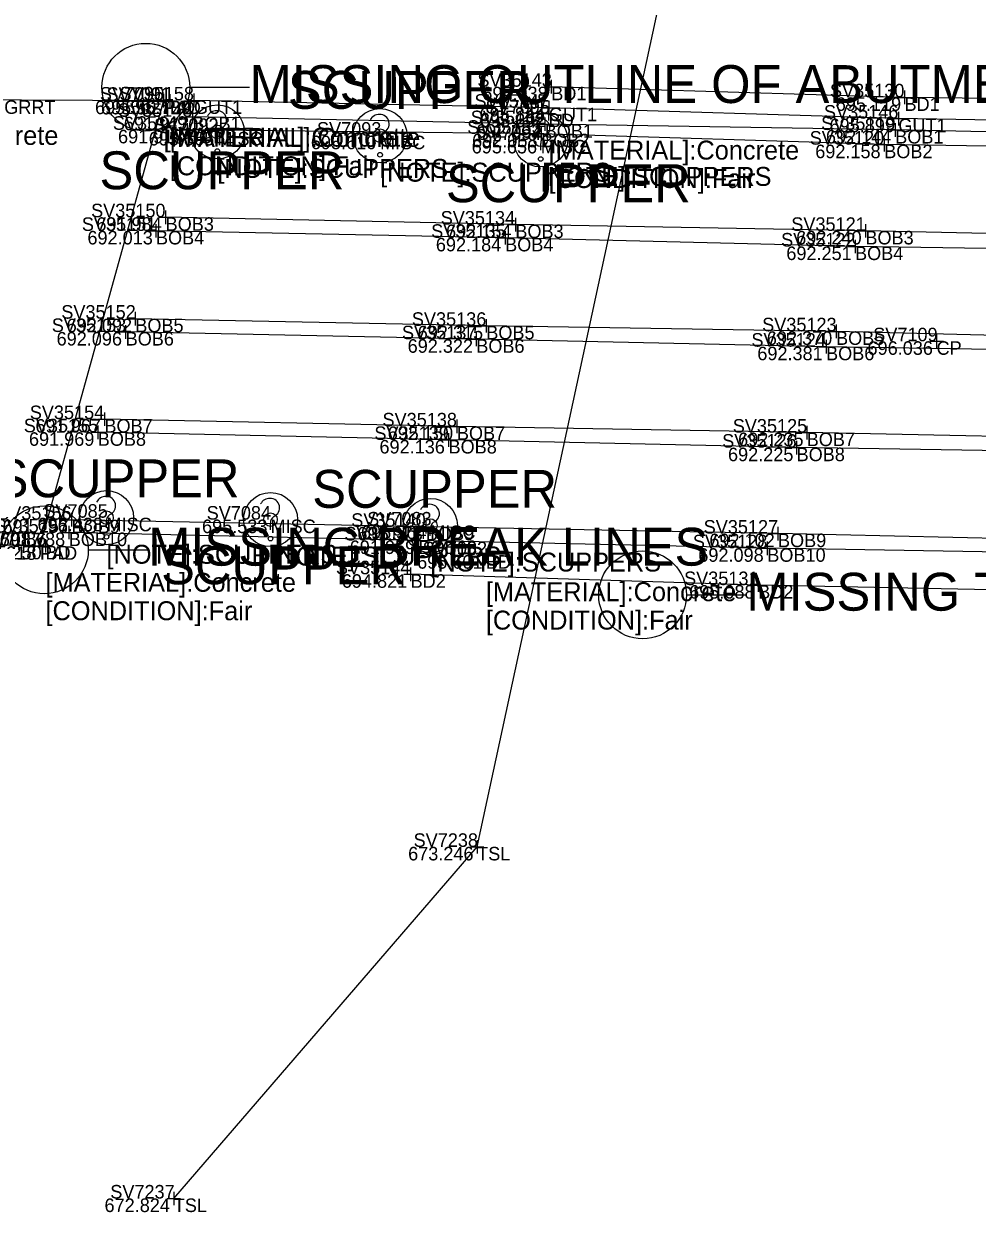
# Model space of a CAD drawing. Extents: x 1660019 to 1662995, y 619975 to 620342.
# Drawn here: x 1661226.1 to 1661296.6, y 620168.6 to 620256.5 of the extents above; entities that cross this region are included whole.
import ezdxf

# ---------------------------------------------------------------- set-up
doc = ezdxf.new("R2010")
doc.units = 0
for name, color, linetype in [('BR_X_Rail_Object', 7, 'Continuous'), ('BR_X_SV_Bottom_of_Beam', 7, 'Continuous'), ('BR_X_SV_Bottom_of_Beam_Text', 7, 'Continuous'), ('BR_X_SV_Deck_Top', 7, 'Continuous'), ('BR_X_SV_Deck_Top_Text', 7, 'Continuous'), ('PV_X_Curb', 7, 'Continuous'), ('RD_P_GR_Lt', 7, 'Continuous'), ('RD_X_Concrete_Pad', 7, 'Continuous'), ('RD_X_GR_Bar', 7, 'Continuous'), ('RD_X_Misc_Items', 7, 'Continuous'), ('RD_X_Text', 7, 'Continuous'), ('RD_X_Wall', 7, 'Continuous'), ('SC_Scratch6', 7, 'Continuous'), ('SV_X_Text', 7, 'Continuous'), ('SV_X_Toe_of_Slope', 7, 'Continuous')]:
    doc.layers.add(name, color=color, linetype=linetype)

msp = doc.modelspace()

# ---------------------------------------------------------------- linework, layer by layer
at = {"layer": 'BR_X_SV_Bottom_of_Beam'}
for points in [[(1661523.404, 620243.849), (1661497.415, 620244.383), (1661471.694, 620244.95), (1661445.773, 620245.45), (1661419.903, 620245.974), (1661394.009, 620246.51), (1661368.147, 620247.032), (1661342.287, 620247.488), (1661316.311, 620248.045), (1661290.557, 620248.602), (1661264.648, 620249.031), (1661238.6, 620249.579)], [(1661517.582, 620243.008), (1661496.897, 620243.44), (1661470.919, 620243.838), (1661445.09, 620244.441), (1661419.147, 620244.946), (1661393.26, 620245.417), (1661367.358, 620245.921), (1661341.629, 620246.518), (1661315.646, 620247.115), (1661289.746, 620247.518), (1661264.383, 620248.322), (1661238.204, 620248.614)], [(1661521.265, 620236.365), (1661495.332, 620236.959), (1661469.491, 620237.512), (1661443.572, 620237.996), (1661417.708, 620238.508), (1661391.884, 620239.08), (1661365.994, 620239.561), (1661340.119, 620240.034), (1661314.197, 620240.589), (1661288.354, 620241.145), (1661262.476, 620241.611), (1661236.623, 620242.15)], [(1661520.605, 620235.452), (1661494.63, 620235.975), (1661468.71, 620236.383), (1661442.944, 620236.996), (1661417.103, 620237.514), (1661391.103, 620237.982), (1661365.202, 620238.448), (1661339.374, 620239.07), (1661313.502, 620239.591), (1661287.59, 620239.99), (1661261.723, 620240.632), (1661235.908, 620241.144)], [(1661519.081, 620228.953), (1661493.234, 620229.438), (1661467.368, 620230.031), (1661441.422, 620230.57), (1661415.6, 620231.071), (1661389.731, 620231.651), (1661363.823, 620232.132), (1661337.817, 620232.613), (1661311.988, 620233.076), (1661286.183, 620233.721), (1661260.328, 620234.129), (1661234.382, 620234.656)], [(1661518.51, 620227.977), (1661492.527, 620228.475), (1661466.56, 620228.954), (1661440.742, 620229.56), (1661414.823, 620230.069), (1661388.938, 620230.522), (1661363.07, 620231.021), (1661337.298, 620231.612), (1661311.527, 620232.162), (1661285.446, 620232.587), (1661259.588, 620233.138), (1661233.669, 620233.674)], [(1661516.938, 620221.488), (1661491.079, 620222.019), (1661465.187, 620222.58), (1661439.251, 620223.092), (1661413.441, 620223.61), (1661387.584, 620224.174), (1661361.703, 620224.657), (1661335.742, 620225.126), (1661309.876, 620225.693), (1661284.015, 620226.238), (1661258.155, 620226.696), (1661232.1, 620227.235)], [(1661516.255, 620220.542), (1661490.624, 620220.907), (1661464.53, 620221.454), (1661438.64, 620222.101), (1661412.707, 620222.613), (1661386.76, 620223.066), (1661360.949, 620223.557), (1661335.05, 620224.176), (1661309.206, 620224.717), (1661283.267, 620225.126), (1661257.537, 620225.694), (1661231.605, 620226.262)], [(1661514.756, 620214.059), (1661488.914, 620214.555), (1661463.017, 620215.148), (1661437.126, 620215.616), (1661411.256, 620216.167), (1661385.428, 620216.691), (1661359.541, 620217.184), (1661333.602, 620217.682), (1661307.754, 620218.183), (1661281.891, 620218.773), (1661255.858, 620219.275), (1661229.67, 620219.799)], [(1661514.073, 620213.08), (1661488.21, 620213.597), (1661462.263, 620214.044), (1661436.515, 620214.643), (1661410.516, 620215.165), (1661384.602, 620215.601), (1661358.815, 620216.084), (1661332.968, 620216.701), (1661307.113, 620217.251), (1661281.101, 620217.691), (1661255.319, 620218.266), (1661229.464, 620218.851)]]:
    msp.add_lwpolyline(points, dxfattribs=at)
at = {"layer": 'BR_X_SV_Deck_Top'}
for points in [[(1661524.154, 620246.519), (1661498.291, 620247.067), (1661472.426, 620247.598), (1661446.524, 620248.074), (1661420.55, 620248.604), (1661394.772, 620249.021), (1661368.927, 620249.743), (1661342.743, 620250.117), (1661316.866, 620250.706), (1661291.246, 620251.013), (1661265.132, 620251.796)], [(1661513.529, 620210.295), (1661487.664, 620211.099), (1661461.66, 620211.354), (1661435.632, 620211.885), (1661409.962, 620212.424), (1661383.838, 620212.928), (1661332.298, 620213.947), (1661306.248, 620214.439), (1661280.429, 620214.969), (1661254.732, 620215.771)]]:
    msp.add_lwpolyline(points, dxfattribs=at)
at = {"layer": 'PV_X_Curb'}
msp.add_lwpolyline([(1661523.342, 620245.121), (1661471.566, 620246.113), (1661445.996, 620246.597), (1661316.22, 620249.01), (1661290.79, 620249.439), (1661264.952, 620250.247), (1661238.714, 620250.79)], dxfattribs=at)
at = {"layer": 'RD_P_GR_Lt'}
for p, q in [((1661265.132, 620252.296), (1661265.132, 620251.296)), ((1661236.479, 620251.273), (1661236.479, 620250.273)), ((1661236.937, 620251.254), (1661236.937, 620250.254)), ((1661238.714, 620251.29), (1661238.714, 620250.29)), ((1661264.632, 620251.796), (1661265.632, 620251.796)), ((1661265.132, 620251.796), (1661265.132, 620251.796)), ((1661291.246, 620251.513), (1661291.246, 620250.513)), ((1661235.979, 620250.773), (1661236.979, 620250.773)), ((1661236.437, 620250.754), (1661237.437, 620250.754)), ((1661236.479, 620250.773), (1661236.479, 620250.773)), ((1661236.937, 620250.754), (1661236.937, 620250.754)), ((1661238.214, 620250.79), (1661239.214, 620250.79)), ((1661238.714, 620250.79), (1661238.714, 620250.79)), ((1661264.939, 620250.315), (1661264.939, 620249.315)), ((1661264.952, 620250.747), (1661264.952, 620249.747)), ((1661290.746, 620251.013), (1661291.746, 620251.013)), ((1661291.246, 620251.013), (1661291.246, 620251.013)), ((1661238.1, 620249.579), (1661239.1, 620249.579)), ((1661238.6, 620250.079), (1661238.6, 620249.079)), ((1661238.6, 620249.579), (1661238.6, 620249.579)), ((1661264.439, 620249.815), (1661265.439, 620249.815)), ((1661264.452, 620250.247), (1661265.452, 620250.247)), ((1661264.648, 620249.531), (1661264.648, 620248.531)), ((1661264.939, 620249.815), (1661264.939, 620249.815)), ((1661264.952, 620250.247), (1661264.952, 620250.247)), ((1661290.29, 620249.439), (1661291.29, 620249.439)), ((1661290.79, 620249.939), (1661290.79, 620248.939)), ((1661290.79, 620249.439), (1661290.79, 620249.439)), ((1661237.704, 620248.614), (1661238.704, 620248.614)), ((1661238.204, 620249.114), (1661238.204, 620248.114)), ((1661238.204, 620248.614), (1661238.204, 620248.614)), ((1661264.148, 620249.031), (1661265.148, 620249.031)), ((1661264.383, 620248.822), (1661264.383, 620247.822)), ((1661264.648, 620249.031), (1661264.648, 620249.031)), ((1661290.057, 620248.602), (1661291.057, 620248.602)), ((1661290.557, 620249.102), (1661290.557, 620248.102)), ((1661290.557, 620248.602), (1661290.557, 620248.602)), ((1661263.883, 620248.322), (1661264.883, 620248.322)), ((1661264.383, 620248.322), (1661264.383, 620248.322)), ((1661289.746, 620248.018), (1661289.746, 620247.018)), ((1661289.246, 620247.518), (1661290.246, 620247.518)), ((1661289.746, 620247.518), (1661289.746, 620247.518)), ((1661236.623, 620242.65), (1661236.623, 620241.65)), ((1661235.908, 620241.644), (1661235.908, 620240.644)), ((1661236.123, 620242.15), (1661237.123, 620242.15)), ((1661236.623, 620242.15), (1661236.623, 620242.15)), ((1661261.976, 620241.611), (1661262.976, 620241.611)), ((1661262.476, 620242.111), (1661262.476, 620241.111)), ((1661262.476, 620241.611), (1661262.476, 620241.611)), ((1661288.354, 620241.645), (1661288.354, 620240.645)), ((1661235.408, 620241.144), (1661236.408, 620241.144)), ((1661235.908, 620241.144), (1661235.908, 620241.144)), ((1661261.723, 620241.132), (1661261.723, 620240.132)), ((1661287.854, 620241.145), (1661288.854, 620241.145)), ((1661288.354, 620241.145), (1661288.354, 620241.145)), ((1661261.223, 620240.632), (1661262.223, 620240.632)), ((1661261.723, 620240.632), (1661261.723, 620240.632)), ((1661287.09, 620239.99), (1661288.09, 620239.99)), ((1661287.59, 620240.49), (1661287.59, 620239.49)), ((1661287.59, 620239.99), (1661287.59, 620239.99)), ((1661233.882, 620234.656), (1661234.882, 620234.656)), ((1661234.382, 620235.156), (1661234.382, 620234.156)), ((1661234.382, 620234.656), (1661234.382, 620234.656)), ((1661260.328, 620234.629), (1661260.328, 620233.629)), ((1661233.169, 620233.674), (1661234.169, 620233.674)), ((1661233.669, 620234.174), (1661233.669, 620233.174)), ((1661233.669, 620233.674), (1661233.669, 620233.674)), ((1661259.588, 620233.638), (1661259.588, 620232.638)), ((1661259.828, 620234.129), (1661260.828, 620234.129)), ((1661260.328, 620234.129), (1661260.328, 620234.129)), ((1661285.683, 620233.721), (1661286.683, 620233.721)), ((1661286.183, 620234.221), (1661286.183, 620233.221)), ((1661286.183, 620233.721), (1661286.183, 620233.721)), ((1661259.088, 620233.138), (1661260.088, 620233.138)), ((1661259.588, 620233.138), (1661259.588, 620233.138)), ((1661285.446, 620233.087), (1661285.446, 620232.087)), ((1661293.115, 620232.986), (1661294.115, 620232.986)), ((1661293.615, 620233.486), (1661293.615, 620232.486)), ((1661293.615, 620232.986), (1661293.615, 620232.986)), ((1661284.946, 620232.587), (1661285.946, 620232.587)), ((1661285.446, 620232.587), (1661285.446, 620232.587)), ((1661232.1, 620227.735), (1661232.1, 620226.735)), ((1661231.6, 620227.235), (1661232.6, 620227.235)), ((1661231.605, 620226.762), (1661231.605, 620225.762)), ((1661232.1, 620227.235), (1661232.1, 620227.235)), ((1661257.655, 620226.696), (1661258.655, 620226.696)), ((1661258.155, 620227.196), (1661258.155, 620226.196)), ((1661258.155, 620226.696), (1661258.155, 620226.696)), ((1661284.015, 620226.738), (1661284.015, 620225.738)), ((1661231.105, 620226.262), (1661232.105, 620226.262)), ((1661231.605, 620226.262), (1661231.605, 620226.262)), ((1661257.537, 620226.194), (1661257.537, 620225.194)), ((1661283.515, 620226.238), (1661284.515, 620226.238)), ((1661284.015, 620226.238), (1661284.015, 620226.238)), ((1661257.037, 620225.694), (1661258.037, 620225.694)), ((1661257.537, 620225.694), (1661257.537, 620225.694)), ((1661282.767, 620225.126), (1661283.767, 620225.126)), ((1661283.267, 620225.626), (1661283.267, 620224.626)), ((1661283.267, 620225.126), (1661283.267, 620225.126)), ((1661229.17, 620219.799), (1661230.17, 620219.799)), ((1661229.67, 620220.299), (1661229.67, 620219.299)), ((1661229.67, 620219.799), (1661229.67, 620219.799)), ((1661255.858, 620219.775), (1661255.858, 620218.775)), ((1661228.964, 620218.851), (1661229.964, 620218.851)), ((1661229.464, 620219.351), (1661229.464, 620218.351)), ((1661229.464, 620218.851), (1661229.464, 620218.851)), ((1661255.319, 620218.766), (1661255.319, 620217.766)), ((1661255.358, 620219.275), (1661256.358, 620219.275)), ((1661255.858, 620219.275), (1661255.858, 620219.275)), ((1661281.391, 620218.773), (1661282.391, 620218.773)), ((1661281.891, 620219.273), (1661281.891, 620218.273)), ((1661281.891, 620218.773), (1661281.891, 620218.773)), ((1661226.837, 620217.837), (1661227.837, 620217.837)), ((1661227.242, 620217.874), (1661228.242, 620217.874)), ((1661227.337, 620218.337), (1661227.337, 620217.337)), ((1661227.337, 620217.837), (1661227.337, 620217.837)), ((1661227.742, 620218.374), (1661227.742, 620217.374)), ((1661227.742, 620217.874), (1661227.742, 620217.874)), ((1661254.819, 620218.266), (1661255.819, 620218.266)), ((1661255.319, 620218.266), (1661255.319, 620218.266)), ((1661281.101, 620218.191), (1661281.101, 620217.191)), ((1661259.798, 620217.181), (1661260.798, 620217.181)), ((1661260.298, 620217.681), (1661260.298, 620216.681)), ((1661260.298, 620217.181), (1661260.298, 620217.181)), ((1661280.601, 620217.691), (1661281.601, 620217.691)), ((1661281.101, 620217.691), (1661281.101, 620217.691)), ((1661254.732, 620216.271), (1661254.732, 620215.271)), ((1661254.232, 620215.771), (1661255.232, 620215.771)), ((1661254.732, 620215.771), (1661254.732, 620215.771)), ((1661280.429, 620215.469), (1661280.429, 620214.469)), ((1661279.929, 620214.969), (1661280.929, 620214.969)), ((1661280.429, 620214.969), (1661280.429, 620214.969)), ((1661259.655, 620196.123), (1661259.655, 620195.123)), ((1661259.155, 620195.623), (1661260.155, 620195.623)), ((1661259.655, 620195.623), (1661259.655, 620195.623)), ((1661236.729, 620169.637), (1661237.729, 620169.637)), ((1661237.229, 620170.137), (1661237.229, 620169.137)), ((1661237.229, 620169.637), (1661237.229, 620169.637))]:
    msp.add_line(p, q, dxfattribs=at)
at = {"layer": 'RD_X_Concrete_Pad'}
msp.add_lwpolyline([(1661227.337, 620217.837), (1661200.851, 620218.632), (1661210.18, 620250.901), (1661236.479, 620250.773)], close=True, dxfattribs=at)
at = {"layer": 'RD_X_Misc_Items'}
for p, q in [((1661240.447, 620247.706), (1661240.447, 620248.181)), ((1661252.475, 620247.427), (1661252.475, 620247.902)), ((1661264.352, 620247.116), (1661264.352, 620247.591)), ((1661232.255, 620219.193), (1661232.255, 620219.668)), ((1661244.378, 620219.055), (1661244.378, 620219.53)), ((1661256.189, 620218.618), (1661256.189, 620219.093))]:
    msp.add_line(p, q, dxfattribs=at)
for centre, radius in [((1661240.447, 620248.461), 2), ((1661252.475, 620248.182), 2), ((1661264.352, 620247.871), 2), ((1661240.447, 620248.461), 0.5), ((1661252.475, 620248.182), 0.5), ((1661264.352, 620247.871), 0.5), ((1661240.447, 620247.049), 0.17), ((1661252.475, 620246.77), 0.17), ((1661264.352, 620246.459), 0.17), ((1661232.255, 620219.948), 2), ((1661244.378, 620219.81), 2), ((1661256.189, 620219.373), 2), ((1661232.255, 620219.948), 0.5), ((1661244.378, 620219.81), 0.5), ((1661256.189, 620219.373), 0.5), ((1661232.255, 620218.536), 0.17), ((1661244.378, 620218.398), 0.17), ((1661256.189, 620217.961), 0.17)]:
    msp.add_circle(centre, radius, dxfattribs=at)
for centre, radius, start, end in [((1661240.383, 620249.272), 0.754, 88.32401, 152.53853), ((1661240.435, 620249.339), 0.688, 291.93294, 92.45835), ((1661252.411, 620248.993), 0.754, 88.32401, 152.53853), ((1661252.463, 620249.06), 0.688, 291.93294, 92.45835), ((1661264.288, 620248.682), 0.754, 88.32401, 152.53853), ((1661264.34, 620248.749), 0.688, 291.93294, 92.45835), ((1661241.033, 620248.223), 0.587, 125.46179, 184.08291), ((1661253.061, 620247.944), 0.587, 125.46179, 184.08291), ((1661264.938, 620247.633), 0.587, 125.46179, 184.08291), ((1661232.191, 620220.759), 0.754, 88.32401, 152.53853), ((1661232.243, 620220.826), 0.688, 291.93294, 92.45835), ((1661244.314, 620220.621), 0.754, 88.32401, 152.53853), ((1661244.366, 620220.688), 0.688, 291.93294, 92.45835), ((1661256.125, 620220.184), 0.754, 88.32401, 152.53853), ((1661256.177, 620220.251), 0.688, 291.93294, 92.45835), ((1661232.841, 620219.71), 0.587, 125.46179, 184.08291), ((1661244.964, 620219.572), 0.587, 125.46179, 184.08291), ((1661256.775, 620219.135), 0.587, 125.46179, 184.08291)]:
    msp.add_arc(centre, radius, start, end, dxfattribs=at)
at = {"layer": 'SC_Scratch6'}
for p, q in [((1661238.401, 620251.76), (1661242.831, 620251.76)), ((1661230.904, 620217.573), (1661235.334, 620217.573)), ((1661275.127, 620214.246), (1661279.557, 620214.246))]:
    msp.add_line(p, q, dxfattribs=at)
for centre in [(1661235.157, 620251.76), (1661227.66, 620217.573), (1661271.883, 620214.246)]:
    msp.add_circle(centre, 3.245, dxfattribs=at)
at = {"layer": 'SV_X_Toe_of_Slope'}
msp.add_lwpolyline([(1661237.229, 620169.637), (1661259.655, 620195.623), (1661277.405, 620277.795), (1661264.309, 620300.267)], dxfattribs=at)

# ---------------------------------------------------------------- texts
at = {"layer": 'BR_X_Rail_Object'}
for s, p in [('GRRT', (1661224.694, 620249.792)), ('PAD', (1661236.479, 620249.773)), ('GUT1', (1661238.714, 620249.79)), ('GUT1', (1661264.952, 620249.247)), ('GUT1', (1661290.79, 620248.439)), ('MISC', (1661240.447, 620247.461)), ('MISC', (1661252.475, 620247.182)), ('MISC', (1661264.352, 620246.871)), ('CP', (1661293.615, 620231.986)), ('MISC', (1661232.255, 620218.948)), ('MISC', (1661244.378, 620218.81)), ('MISC', (1661256.189, 620218.373)), ('PAD', (1661227.337, 620216.837)), ('TSL', (1661259.655, 620194.623)), ('TSL', (1661237.229, 620168.637))]:
    msp.add_text(s, height=1, dxfattribs=at).set_placement(p)
at = {"layer": 'BR_X_SV_Bottom_of_Beam_Text'}
for s, p in [('SV35148', (1661233.103, 620249.579)), ('SV35149', (1661232.724, 620248.614)), ('691.913', (1661233.536, 620248.579)), ('BOB1', (1661238.6, 620248.579)), ('SV35132', (1661259.179, 620249.031)), ('SV35119', (1661285.077, 620248.602)), ('691.918', (1661233.104, 620247.614)), ('BOB2', (1661238.204, 620247.614)), ('SV35133', (1661258.923, 620248.322)), ('692.052', (1661259.575, 620248.031)), ('BOB1', (1661264.648, 620248.031)), ('692.144', (1661285.435, 620247.602)), ('BOB1', (1661290.557, 620247.602)), ('692.058', (1661259.283, 620247.322)), ('BOB2', (1661264.383, 620247.322)), ('SV35120', (1661284.236, 620247.518)), ('692.158', (1661284.646, 620246.518)), ('BOB2', (1661289.746, 620246.518)), ('SV35150', (1661231.113, 620242.15)), ('SV35134', (1661256.958, 620241.611)), ('SV35151', (1661230.43, 620241.144)), ('691.984', (1661231.501, 620241.15)), ('BOB3', (1661236.623, 620241.15)), ('SV35135', (1661256.256, 620240.632)), ('692.154', (1661257.354, 620240.611)), ('BOB3', (1661262.476, 620240.611)), ('SV35121', (1661282.876, 620241.145)), ('692.013', (1661230.844, 620240.144)), ('BOB4', (1661235.908, 620240.144)), ('SV35122', (1661282.121, 620239.99)), ('692.240', (1661283.24, 620240.145)), ('BOB3', (1661288.354, 620240.145)), ('692.184', (1661256.601, 620239.632)), ('BOB4', (1661261.723, 620239.632)), ('692.251', (1661282.508, 620238.99)), ('BOB4', (1661287.59, 620238.99)), ('SV35152', (1661228.913, 620234.656)), ('SV35153', (1661228.209, 620233.674)), ('692.092', (1661229.309, 620233.656)), ('BOB5', (1661234.382, 620233.656)), ('SV35136', (1661254.828, 620234.129)), ('SV35123', (1661280.723, 620233.721)), ('692.096', (1661228.565, 620232.674)), ('BOB6', (1661233.669, 620232.674)), ('SV35137', (1661254.096, 620233.138)), ('692.315', (1661255.258, 620233.129)), ('BOB5', (1661260.328, 620233.129)), ('692.370', (1661281.069, 620232.721)), ('BOB5', (1661286.183, 620232.721)), ('692.322', (1661254.515, 620232.138)), ('BOB6', (1661259.588, 620232.138)), ('SV35124', (1661279.928, 620232.587)), ('692.381', (1661280.364, 620231.587)), ('BOB6', (1661285.446, 620231.587)), ('SV35154', (1661226.582, 620227.235)), ('SV35138', (1661252.658, 620226.696)), ('SV35155', (1661226.138, 620226.262)), ('691.967', (1661227.004, 620226.235)), ('BOB7', (1661232.1, 620226.235)), ('SV35139', (1661252.057, 620225.694)), ('692.150', (1661253.041, 620225.696)), ('BOB7', (1661258.155, 620225.696)), ('SV35125', (1661278.548, 620226.238)), ('691.969', (1661226.521, 620225.262)), ('BOB8', (1661231.605, 620225.262)), ('SV35126', (1661277.767, 620225.126)), ('692.235', (1661278.945, 620225.238)), ('BOB7', (1661284.015, 620225.238)), ('692.136', (1661252.433, 620224.694)), ('BOB8', (1661257.537, 620224.694)), ('692.225', (1661278.197, 620224.126)), ('BOB8', (1661283.267, 620224.126)), ('SV35156', (1661224.17, 620219.799)), ('SV35157', (1661223.972, 620218.851)), ('691.796', (1661224.566, 620218.799)), ('BOB9', (1661229.67, 620218.799)), ('SV35140', (1661250.348, 620219.275)), ('SV35127', (1661276.399, 620218.773)), ('691.788', (1661224.364, 620217.851)), ('BOB10', (1661229.464, 620217.851)), ('SV35141', (1661249.841, 620218.266)), ('691.973', (1661250.794, 620218.275)), ('BOB9', (1661255.858, 620218.275)), ('SV35128', (1661275.604, 620217.691)), ('692.102', (1661276.818, 620217.773)), ('BOB9', (1661281.891, 620217.773)), ('691.959', (1661250.235, 620217.266)), ('BOB10', (1661255.319, 620217.266)), ('692.098', (1661276.001, 620216.691)), ('BOB10', (1661281.101, 620216.691))]:
    msp.add_text(s, height=1, dxfattribs=at).set_placement(p)
at = {"layer": 'BR_X_SV_Deck_Top_Text'}
for s, p in [('SV35143', (1661259.672, 620251.796)), ('SV7091', (1661232.257, 620250.754)), ('695.038', (1661260.032, 620250.796)), ('BD1', (1661265.132, 620250.796)), ('SV35130', (1661285.736, 620251.013)), ('695.507', (1661231.841, 620249.754)), ('BD', (1661236.937, 620249.754)), ('SV7095', (1661260.27, 620249.815)), ('695.119', (1661286.162, 620250.013)), ('BD1', (1661291.246, 620250.013)), ('695.692', (1661259.866, 620248.815)), ('BD', (1661264.939, 620248.815)), ('SV7086', (1661223.04, 620217.874)), ('695.250', (1661222.628, 620216.874)), ('BD', (1661227.742, 620216.874)), ('SV7082', (1661255.627, 620217.181)), ('695.601', (1661255.216, 620216.181)), ('BD', (1661260.298, 620216.181)), ('SV35144', (1661249.214, 620215.771)), ('694.821', (1661249.65, 620214.771)), ('BD2', (1661254.732, 620214.771)), ('SV35131', (1661274.951, 620214.969)), ('695.088', (1661275.329, 620213.969)), ('BD2', (1661280.429, 620213.969))]:
    msp.add_text(s, height=1, dxfattribs=at).set_placement(p)
at = {"layer": 'RD_X_GR_Bar'}
for s, p in [('695.502', (1661231.406, 620249.773)), ('695.709', (1661233.63, 620249.79)), ('695.844', (1661259.83, 620249.247)), ('695.899', (1661285.706, 620248.439)), ('695.565', (1661235.377, 620247.461)), ('695.610', (1661247.361, 620247.182)), ('695.656', (1661259.248, 620246.871)), ('696.036', (1661288.511, 620231.986)), ('695.438', (1661227.155, 620218.948)), ('695.533', (1661239.314, 620218.81)), ('695.564', (1661251.067, 620218.373)), ('695.218', (1661222.237, 620216.837)), ('673.246', (1661254.551, 620194.623)), ('672.824', (1661232.107, 620168.637))]:
    msp.add_text(s, height=1, dxfattribs=at).set_placement(p)
at = {"layer": 'RD_X_Text'}
for p in [(1661245.663, 620250.164), (1661231.736, 620244.222), (1661257.344, 620243.265), (1661223.988, 620221.459), (1661247.461, 620220.68), (1661236.292, 620215.027)]:
    msp.add_text('SCUPPER', height=2.8, dxfattribs=at).set_placement(p)
at = {"layer": 'RD_X_Wall'}
for s, p in [('SV7090', (1661231.767, 620250.773)), ('SV35158', (1661233.217, 620250.79)), ('SV35147', (1661259.46, 620250.247)), ('SV35146', (1661285.29, 620249.439)), ('SV7092', (1661235.776, 620248.461)), ('SV7093', (1661247.813, 620248.182)), ('SV7094', (1661259.632, 620247.871)), ('SV7109', (1661288.933, 620232.986)), ('SV7085', (1661227.586, 620219.948)), ('SV7084', (1661239.658, 620219.81)), ('SV7083', (1661251.527, 620219.373)), ('SV7087', (1661222.643, 620217.837)), ('SV7238', (1661254.956, 620195.623)), ('SV7237', (1661232.535, 620169.637))]:
    msp.add_text(s, height=1, dxfattribs=at).set_placement(p)
at = {"layer": 'SC_Scratch6'}
for s, p in [('MISSING OUTLINE OF ABUTMENT', (1661242.831, 620250.594)), ('MISSING BREAK LINES', (1661235.334, 620216.406)), ('MISSING TOE OF BARRIER', (1661279.557, 620213.079))]:
    msp.add_text(s, height=2.79999, dxfattribs=at).set_placement(p)
at = {"layer": 'SV_X_Text'}
for s, p in [('[MATERIAL]:Concrete', (1661210.18, 620247.501)), ('[MATERIAL]:Concrete', (1661236.479, 620247.373)), ('[MATERIAL]:Concrete', (1661236.937, 620247.354)), ('[MATERIAL]:Concrete', (1661264.939, 620246.415)), ('[CONDITION]:Fair', (1661236.937, 620245.254)), ('[NOTE]:SCUPPERS', (1661240.447, 620245.061)), ('[NOTE]:SCUPPERS', (1661252.475, 620244.782)), ('[NOTE]:SCUPPERS', (1661264.352, 620244.471)), ('[CONDITION]:Fair', (1661264.939, 620244.315)), ('[NOTE]:SCUPPERS', (1661232.255, 620216.548)), ('[NOTE]:SCUPPERS', (1661244.378, 620216.41)), ('[NOTE]:SCUPPERS', (1661256.189, 620215.973)), ('[MATERIAL]:Concrete', (1661227.742, 620214.474)), ('[MATERIAL]:Concrete', (1661260.298, 620213.781)), ('[CONDITION]:Fair', (1661227.742, 620212.374)), ('[CONDITION]:Fair', (1661260.298, 620211.681))]:
    msp.add_text(s, height=1.4, dxfattribs=at).set_placement(p)

doc.saveas('drawing.dxf')
